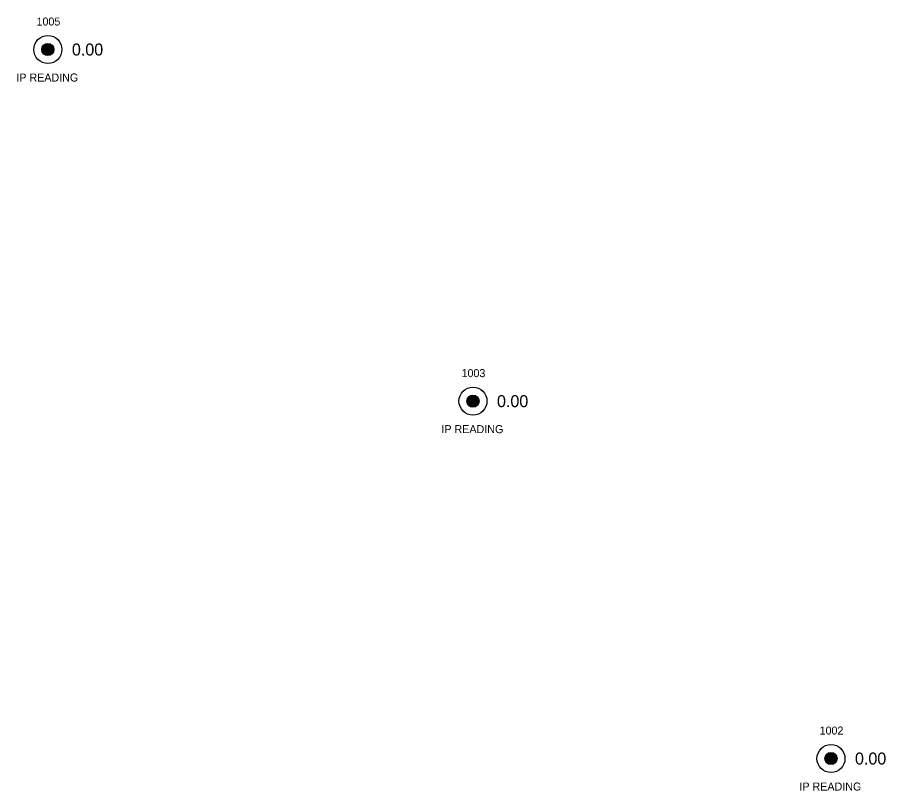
# Model space of a CAD drawing. Extents: x 1448136 to 1453623, y 1125056 to 1128842.
# Drawn here: x 1452388.8 to 1452497.3, y 1126934.9 to 1127031.6 of the extents above; entities that cross this region are included whole.
import ezdxf

# ---------------------------------------------------------------- set-up
doc = ezdxf.new("R2010")
doc.units = 0
for name, color, linetype in [('RD_EX_DV_Prop_txCode', 7, 'Continuous'), ('RD_EX_DV_PropPin', 7, 'Continuous'), ('RD_EX_TX_DV_Prop_ELEV', 7, 'Continuous'), ('RD_SMD_Locator', 7, 'Continuous')]:
    doc.layers.add(name, color=color, linetype=linetype)

msp = doc.modelspace()

# ---------------------------------------------------------------- linework, layer by layer
at = {"layer": 'RD_EX_DV_PropPin'}
for p, q in [((1452392.07, 1127027.08), (1452392.07, 1127028.03)), ((1452392.1, 1127027.04), (1452392.1, 1127028.07)), ((1452392.14, 1127027), (1452392.14, 1127028.1)), ((1452392.17, 1127026.97), (1452392.17, 1127028.14)), ((1452392.21, 1127026.94), (1452392.21, 1127028.16)), ((1452392.24, 1127026.92), (1452392.24, 1127028.19)), ((1452392.28, 1127026.9), (1452392.28, 1127028.21)), ((1452392.31, 1127026.88), (1452392.31, 1127028.23)), ((1452392.35, 1127026.86), (1452392.35, 1127028.25)), ((1452392.38, 1127026.85), (1452392.38, 1127028.26)), ((1452392.42, 1127026.83), (1452392.42, 1127028.27)), ((1452392.45, 1127026.82), (1452392.45, 1127028.29)), ((1452392.49, 1127026.81), (1452392.49, 1127028.29)), ((1452392.52, 1127026.81), (1452392.52, 1127028.3)), ((1452392.56, 1127026.8), (1452392.56, 1127028.31)), ((1452392.59, 1127026.8), (1452392.59, 1127028.31)), ((1452392.63, 1127026.79), (1452392.63, 1127028.31)), ((1452392.66, 1127026.79), (1452392.66, 1127028.32)), ((1452392.7, 1127026.79), (1452392.7, 1127028.31)), ((1452392.73, 1127026.8), (1452392.73, 1127028.31)), ((1452392.77, 1127026.8), (1452392.77, 1127028.31)), ((1452392.8, 1127026.81), (1452392.8, 1127028.3)), ((1452392.84, 1127026.81), (1452392.84, 1127028.29)), ((1452392.87, 1127026.82), (1452392.87, 1127028.29)), ((1452392.91, 1127026.83), (1452392.91, 1127028.27)), ((1452392.94, 1127026.85), (1452392.94, 1127028.26)), ((1452392.98, 1127026.86), (1452392.98, 1127028.25)), ((1452393.01, 1127026.88), (1452393.01, 1127028.23)), ((1452393.05, 1127026.9), (1452393.05, 1127028.21)), ((1452393.08, 1127026.92), (1452393.08, 1127028.19)), ((1452393.12, 1127026.94), (1452393.12, 1127028.16)), ((1452393.15, 1127026.97), (1452393.15, 1127028.14)), ((1452393.19, 1127027), (1452393.19, 1127028.1)), ((1452393.22, 1127027.04), (1452393.22, 1127028.07)), ((1452393.26, 1127027.08), (1452393.26, 1127028.03)), ((1452391.93, 1127027.36), (1452391.93, 1127027.75)), ((1452391.96, 1127027.26), (1452391.96, 1127027.85)), ((1452392, 1127027.18), (1452392, 1127027.92)), ((1452392.03, 1127027.13), (1452392.03, 1127027.98)), ((1452393.29, 1127027.13), (1452393.29, 1127027.98)), ((1452393.33, 1127027.18), (1452393.33, 1127027.92)), ((1452393.36, 1127027.26), (1452393.36, 1127027.85)), ((1452393.4, 1127027.36), (1452393.4, 1127027.75)), ((1452445.01, 1126983.4), (1452445.01, 1126983.79)), ((1452445.05, 1126983.3), (1452445.05, 1126983.89)), ((1452445.08, 1126983.23), (1452445.08, 1126983.97)), ((1452445.12, 1126983.17), (1452445.12, 1126984.02)), ((1452445.15, 1126983.12), (1452445.15, 1126984.07)), ((1452445.19, 1126983.08), (1452445.19, 1126984.11)), ((1452445.22, 1126983.05), (1452445.22, 1126984.15)), ((1452445.26, 1126983.01), (1452445.26, 1126984.18)), ((1452445.29, 1126982.99), (1452445.29, 1126984.21)), ((1452445.33, 1126982.96), (1452445.33, 1126984.23)), ((1452445.36, 1126982.94), (1452445.36, 1126984.25)), ((1452445.4, 1126982.92), (1452445.4, 1126984.27)), ((1452445.43, 1126982.9), (1452445.43, 1126984.29)), ((1452445.47, 1126982.89), (1452445.47, 1126984.3)), ((1452445.5, 1126982.88), (1452445.5, 1126984.32)), ((1452445.54, 1126982.87), (1452445.54, 1126984.33)), ((1452445.57, 1126982.86), (1452445.57, 1126984.34)), ((1452445.61, 1126982.85), (1452445.61, 1126984.34)), ((1452445.64, 1126982.84), (1452445.64, 1126984.35)), ((1452445.68, 1126982.84), (1452445.68, 1126984.35)), ((1452445.71, 1126982.84), (1452445.71, 1126984.36)), ((1452445.75, 1126982.84), (1452445.75, 1126984.36)), ((1452445.78, 1126982.84), (1452445.78, 1126984.36)), ((1452445.82, 1126982.84), (1452445.82, 1126984.35)), ((1452445.85, 1126982.84), (1452445.85, 1126984.35)), ((1452445.89, 1126982.85), (1452445.89, 1126984.34)), ((1452445.92, 1126982.86), (1452445.92, 1126984.34)), ((1452445.96, 1126982.87), (1452445.96, 1126984.33)), ((1452445.99, 1126982.88), (1452445.99, 1126984.32)), ((1452446.03, 1126982.89), (1452446.03, 1126984.3)), ((1452446.06, 1126982.9), (1452446.06, 1126984.29)), ((1452446.1, 1126982.92), (1452446.1, 1126984.27)), ((1452446.13, 1126982.94), (1452446.13, 1126984.25)), ((1452446.17, 1126982.96), (1452446.17, 1126984.23)), ((1452446.2, 1126982.99), (1452446.2, 1126984.21)), ((1452446.24, 1126983.01), (1452446.24, 1126984.18)), ((1452446.27, 1126983.05), (1452446.27, 1126984.15)), ((1452446.31, 1126983.08), (1452446.31, 1126984.11)), ((1452446.34, 1126983.12), (1452446.34, 1126984.07)), ((1452446.38, 1126983.17), (1452446.38, 1126984.02)), ((1452446.41, 1126983.23), (1452446.41, 1126983.97)), ((1452446.45, 1126983.3), (1452446.45, 1126983.89)), ((1452446.48, 1126983.4), (1452446.48, 1126983.79)), ((1452489.73, 1126938.74), (1452489.73, 1126939.13)), ((1452489.76, 1126938.63), (1452489.76, 1126939.23)), ((1452489.8, 1126938.56), (1452489.8, 1126939.3)), ((1452489.83, 1126938.51), (1452489.83, 1126939.36)), ((1452489.87, 1126938.46), (1452489.87, 1126939.41)), ((1452489.9, 1126938.42), (1452489.9, 1126939.45)), ((1452489.94, 1126938.38), (1452489.94, 1126939.48)), ((1452489.97, 1126938.35), (1452489.97, 1126939.51)), ((1452490.01, 1126938.32), (1452490.01, 1126939.54)), ((1452490.04, 1126938.3), (1452490.04, 1126939.57)), ((1452490.08, 1126938.28), (1452490.08, 1126939.59)), ((1452490.11, 1126938.26), (1452490.11, 1126939.61)), ((1452490.15, 1126938.24), (1452490.15, 1126939.63)), ((1452490.18, 1126938.22), (1452490.18, 1126939.64)), ((1452490.22, 1126938.21), (1452490.22, 1126939.65)), ((1452490.25, 1126938.2), (1452490.25, 1126939.66)), ((1452490.29, 1126938.19), (1452490.29, 1126939.67)), ((1452490.32, 1126938.18), (1452490.32, 1126939.68)), ((1452490.36, 1126938.18), (1452490.36, 1126939.69)), ((1452490.39, 1126938.17), (1452490.39, 1126939.69)), ((1452490.43, 1126938.17), (1452490.43, 1126939.69)), ((1452490.46, 1126938.17), (1452490.46, 1126939.69)), ((1452490.5, 1126938.17), (1452490.5, 1126939.69)), ((1452490.53, 1126938.17), (1452490.53, 1126939.69)), ((1452490.57, 1126938.18), (1452490.57, 1126939.69)), ((1452490.6, 1126938.18), (1452490.6, 1126939.68)), ((1452490.64, 1126938.19), (1452490.64, 1126939.67)), ((1452490.67, 1126938.2), (1452490.67, 1126939.66)), ((1452490.71, 1126938.21), (1452490.71, 1126939.65)), ((1452490.74, 1126938.22), (1452490.74, 1126939.64)), ((1452490.78, 1126938.24), (1452490.78, 1126939.63)), ((1452490.81, 1126938.26), (1452490.81, 1126939.61)), ((1452490.85, 1126938.28), (1452490.85, 1126939.59)), ((1452490.88, 1126938.3), (1452490.88, 1126939.57)), ((1452490.92, 1126938.32), (1452490.92, 1126939.54)), ((1452490.95, 1126938.35), (1452490.95, 1126939.51)), ((1452490.99, 1126938.38), (1452490.99, 1126939.48)), ((1452491.02, 1126938.42), (1452491.02, 1126939.45)), ((1452491.06, 1126938.46), (1452491.06, 1126939.41)), ((1452491.09, 1126938.51), (1452491.09, 1126939.36)), ((1452491.13, 1126938.56), (1452491.13, 1126939.3)), ((1452491.16, 1126938.63), (1452491.16, 1126939.23)), ((1452491.2, 1126938.74), (1452491.2, 1126939.13))]:
    msp.add_line(p, q, dxfattribs=at)
for centre, radius in [((1452392.66, 1127027.55), 1.75), ((1452392.66, 1127027.55), 0.761), ((1452445.75, 1126983.6), 1.75), ((1452445.75, 1126983.6), 0.761), ((1452490.46, 1126938.93), 1.75), ((1452490.46, 1126938.93), 0.761)]:
    msp.add_circle(centre, radius, dxfattribs=at)
at = {"layer": 'RD_SMD_Locator'}
for centre in [(1452392.66, 1127027.55), (1452445.75, 1126983.6), (1452490.46, 1126938.93)]:
    msp.add_circle(centre, 0.15, dxfattribs=at)

# ---------------------------------------------------------------- texts
at = {"layer": 'RD_EX_DV_Prop_txCode'}
for s, p in [('1005', (1452391.24, 1127030.55)), ('IP READING', (1452388.72, 1127023.55)), ('1003', (1452444.32, 1126986.6)), ('IP READING', (1452441.81, 1126979.6)), ('1002', (1452489.04, 1126941.93)), ('IP READING', (1452486.52, 1126934.93))]:
    msp.add_text(s, height=1, dxfattribs=at).set_placement(p)
at = {"layer": 'RD_EX_TX_DV_Prop_ELEV'}
for p in [(1452395.66, 1127026.8), (1452448.75, 1126982.85), (1452493.46, 1126938.18)]:
    msp.add_text('0.00', height=1.5, dxfattribs=at).set_placement(p)

doc.saveas('drawing.dxf')
